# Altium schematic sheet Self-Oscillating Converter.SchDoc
size A4
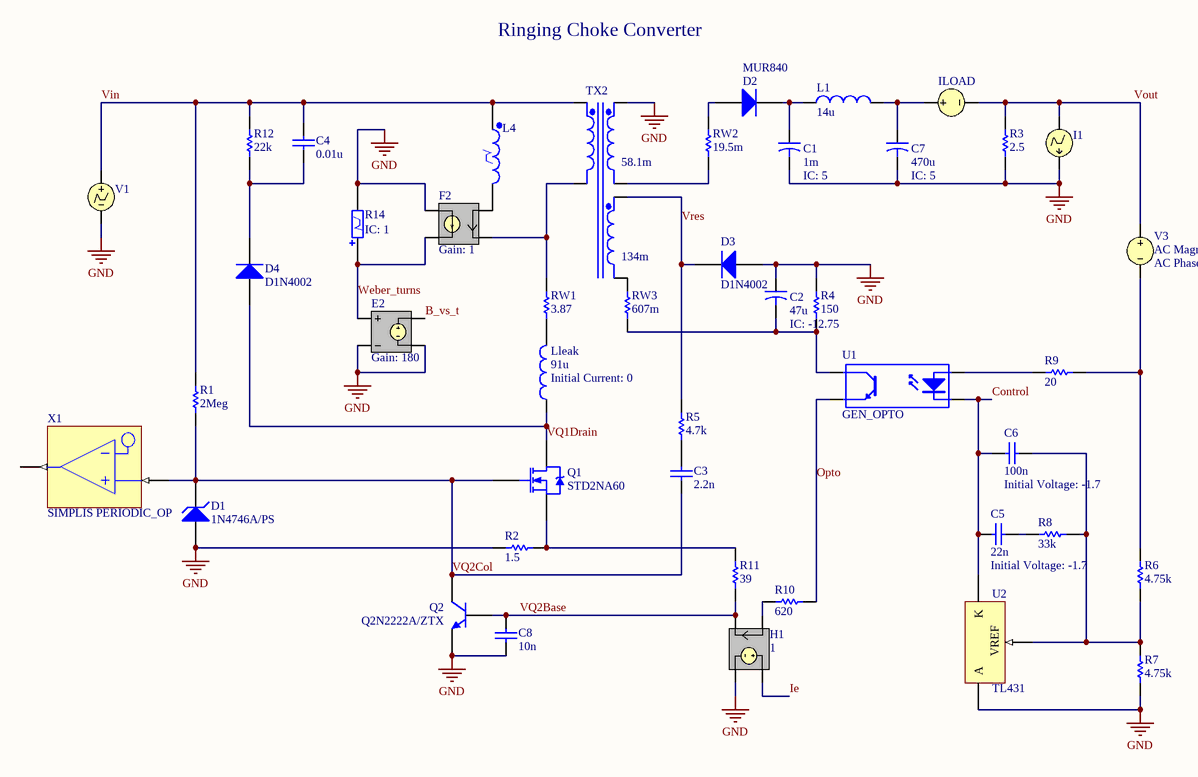
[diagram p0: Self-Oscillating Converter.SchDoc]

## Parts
C1  IC: 5  CC: 1m  [CAPR5-4X5]  (hidden comment: Cap Elec (L1-3))
C2  IC: -12.75  CC: 47u  [CAPR5-4X5]  (hidden comment: Cap Elec (L1-3))
C3  value 2.2n  [RAD-0.3]  (hidden comment: Cap)
C4  value 0.01u  [RAD-0.3]  (hidden comment: Cap)
C5  value 22n  Initial Voltage: -1.7  [RAD-0.3]  (hidden comment: Cap)
C6  value 100n  Initial Voltage: -1.7  [RAD-0.3]  (hidden comment: Cap)
C7  IC: 5  CC: 470u  [CAPR5-4X5]  (hidden comment: Cap Elec (L1-3))
C8  value 10n  [RAD-0.3]  (hidden comment: Cap)
D1  1N4746A/PS  [59-03]
D2  MUR840  [SMC]
D3  D1N4002  [DO-41]
D4  D1N4002  [DO-41]
E2  Gain: 180  (hidden comment: ESRC)
F2  Gain: 1  (hidden comment: FSRC)
H1  Gain: 1  (hidden comment: HSRC)
I1  IPWL  (value not drawn)
ILOAD  VSRC  (value not drawn)
L1  value 14u  [0402-A]  (hidden comment: Lossy Inductor)
L4  SIMPLIS PWLL5  (value not drawn)
Lleak  value 91u  Initial Current: 0  [0402-A]  (hidden comment: Inductor)
Q1  STD2NA60  [TO-220AB]
Q2  Q2N2222A/ZTX  [TO-18]
R1  value 2Meg  [AXIAL-0.3]  (hidden comment: Res1)
R2  value 1.5  [AXIAL-0.3]  (hidden comment: Res1)
R3  value 2.5  [AXIAL-0.3]  (hidden comment: Res1)
R4  value 150  [AXIAL-0.3]  (hidden comment: Res1)
R5  value 4.7k  [AXIAL-0.3]  (hidden comment: Res1)
R6  value 4.75k  [AXIAL-0.3]  (hidden comment: Res1)
R7  value 4.75k  [AXIAL-0.3]  (hidden comment: Res1)
R8  value 33k  [AXIAL-0.3]  (hidden comment: Res1)
R9  value 20  [AXIAL-0.3]  (hidden comment: Res1)
R10  value 620  [AXIAL-0.3]  (hidden comment: Res1)
R11  value 39  [AXIAL-0.3]  (hidden comment: Res1)
R12  value 22k  [AXIAL-0.3]  (hidden comment: Res1)
R14  IC: 1  (hidden comment: SIMPLIS VPWLR5)
RW1  value 3.87  [AXIAL-0.3]  (hidden comment: Res1)
RW2  value 19.5m  [AXIAL-0.3]  (hidden comment: Res1)
RW3  value 607m  [AXIAL-0.3]  (hidden comment: Res1)
TX2  Ratio1: 58.1m  Ratio2: 134m  [TRF_6]  (hidden comment: Trans3 Ideal)
U1  GEN_OPTO  [DIP-4]
U2  TL431  [LP03]
V1  VPWL  (value not drawn)
V3  AC Magnitude: 1  AC Phase: 0  (hidden comment: VSRC)
X1  SIMPLIS PERIODIC_OP

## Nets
GND: C1.2 C2.1 C7.2 C8.2 D1.1(A) D3.1(A) E2.2(NC-) E2.4(N-) F2.3(N+) H1.4(N-) I1.2 Q2.1(E) R2.1 R3.2 R4.1 R7.1 R14.2 TX2.3(Sec1+) U2.2(A) V1.2
B_vs_t: E2.3(N+)
Control: C5.2 C6.2 U1.2(K) U2.3(K)
Ie: H1.3(N+)
Opto: R10.1 U1.3(E)
Vin: C4.1 L4.1 R1.1 R12.1 TX2.1(Pri+) V1.1
Vout: I1.1 ILOAD.2 R3.1 V3.1
VQ1Drain: D4.1(A) Lleak.1 Q1.2(D)
VQ2Base: C8.1 H1.2(NC-) Q2.2(B) R11.1
VQ2Col: C3.1 D1.2(K) Q1.1(G) Q2.3(C) R1.2 X1.1(IN)
Vres: D3.2(K) R5.1 TX2.5(Sec2+)
Weber_turns: E2.1(NC+) F2.4(N-) R14.1
NetC1_1: C1.1 D2.2(K) L1.1
NetC2_2: C2.2 R4.2 RW3.2 U1.4(C)
NetC3_2: C3.2 R5.2
NetC4_2: C4.2 D4.2(K) R12.2
NetC5_1: C5.1 R8.1
NetC6_1: C6.1 R6.1 R7.2 R8.2 U2.1(VREF)
NetC7_1: C7.1 ILOAD.1 L1.2
NetD2_1: D2.1(A) RW2.1
NetF2_1: F2.1(NC+) L4.2
NetF2_2: F2.2(NC-) RW1.1 TX2.2(Pri-)
NetH1_1: H1.1(NC+) R10.2
NetLleak_2: Lleak.2 RW1.2
NetQ1_3: Q1.3(S) R2.2 R11.2
NetR6_2: R6.2 R9.2 V3.2
NetR9_1: R9.1 U1.1(A)
NetRW2_2: RW2.2 TX2.4(Sec1-)
NetRW3_1: RW3.1 TX2.6(Sec2-)

Not connected (* = marked no-connect by the designer): X1 3(OUT)

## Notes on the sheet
- Ringing Choke Converter

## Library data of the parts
C1 = Cap Elec (L1-3): Electrolytic Capacitor (Levels 1-3); LEVEL: 2; RSH_CC: 1Meg; RESR: 40m; USEIC: 1
C2 = Cap Elec (L1-3): Electrolytic Capacitor (Levels 1-3); LEVEL: 2; RSH_CC: 1Meg; RESR: 950m; USEIC: 1
C3-C6 C8 = Cap: Capacitor
C7 = Cap Elec (L1-3): Electrolytic Capacitor (Levels 1-3); LEVEL: 2; RSH_CC: 1Meg; RESR: 290m; USEIC: 1
D1 = 1N4746A/PS: One Watt Hermetically Sealed Glass Silicon Zener Diode
D2 = MUR840: Ultrafast Recovery Rectifier
D3 D4 = D1N4002: 1 Amp General Purpose Rectifier
E2 = ESRC: Voltage Controlled Voltage Source; Note: PCB Footprint - Not required; Sim Note: Enter gain into gain field
F2 = FSRC: Current Controlled Current Source; Note: PCB Footprint - Not required; Sim Note: Enter gain into GAIN field
H1 = HSRC: Current Controlled Voltage Source; Note: PCB Footprint - Not required; Sim Note: Enter gain into gain field
I1 = IPWL: Piecewise Linear Current Source; Sim Note: To add model file containing time-current pairs of values, enter model location under "General Tab" in "Full Path" box.; Time-Value Pairs: 0 0 99.99999u 0 100u 1
ILOAD V3 = VSRC: Voltage Source; Note: PCB Footprint - Not required; Value: 0
L1 = Inductor (Lossy): Code_IEC: 1005; RSERIES: 10m; RSHUNT: 1Meg
L4 = SIMPLIS PWLL5: Piecewise Linear Inductor (5-segment); X0: -0.50; Y0: -1.655m; X1: -0.45; Y1: -1.65m; X2: -0.40; Y2: -1.6m; X3: 0.40; Y3: 1.6m; X4: 0.45; Y4: 1.65m; X5: 0.50; Y5: 1.655m
Lleak = Inductor: Code_IEC: 1005
Q1 = STD2NA60: N-Channel Enhancement Mode Power MOS Transistor; Note: Pin 2 is electrically connected to pin 4.
Q2 = Q2N2222A/ZTX: Zetex General Purpose Transistor NPN Silicon
R1-R12 RW1-RW3 = Res1: Resistor
R14 = SIMPLIS VPWLR5: Voltage-Controlled Piecewise Linear Resistor (5-segment); X0: -1.655m; Y0: -0.5; X1: -1.65m; Y1: -0.45; X2: -1.6m; Y2: -0.4; X3: 1.6m; Y3: 0.4; X4: 1.65m; Y4: 0.45; X5: 1.655m; Y5: 0.5
TX2 = Trans3 Ideal: Three-winding Transformer (Ideal)
U1 = GEN_OPTO: General-Purpose Optocoupler
U2 = TL431: Adjustable Precision Shunt Regulator
V1 = VPWL: Piecewise Linear Voltage Source; Note: PCB Footprint - Not required; Sim Note: To add model file containing time-current pairs of values, enter model location under "General Tab" in "Full Path" box.; Time-Value Pairs: 0 310 0 310 10u 310
X1 = SIMPLIS PERIODIC_OP: Periodic Operating Point Analysis Trigger; XilinxEquivalent: XNOR2; FunctionalClass: Logic Primitive; SubClass: XNOR; PortSize: 2; PortStyle: Single Pin Version; ArchiveName: GENERIC; VHDLIB_SIM: GENERIC_LIB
